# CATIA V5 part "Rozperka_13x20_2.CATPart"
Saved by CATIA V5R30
Part number: Rozperka_13x20_2
Definition: ISO 13337-13x20_1
Nomenclature: ISO 13337-13x20_1
Source: Unknown
Description: PART--DESC
Bounding box of the stored display mesh (mm): x 123 to 135.975, y -24.994 to -12.006, z 29.7 to 49.7
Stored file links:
  E:\Bakalarka\Model\Forma_v7\Rozperka_13x20_2.CATPart
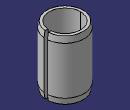
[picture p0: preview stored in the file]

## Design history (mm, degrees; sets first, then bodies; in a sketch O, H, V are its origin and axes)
Body1 "MANIFOLD_SOLID_BREP #3690" (main body)
  Solid1: solid without history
